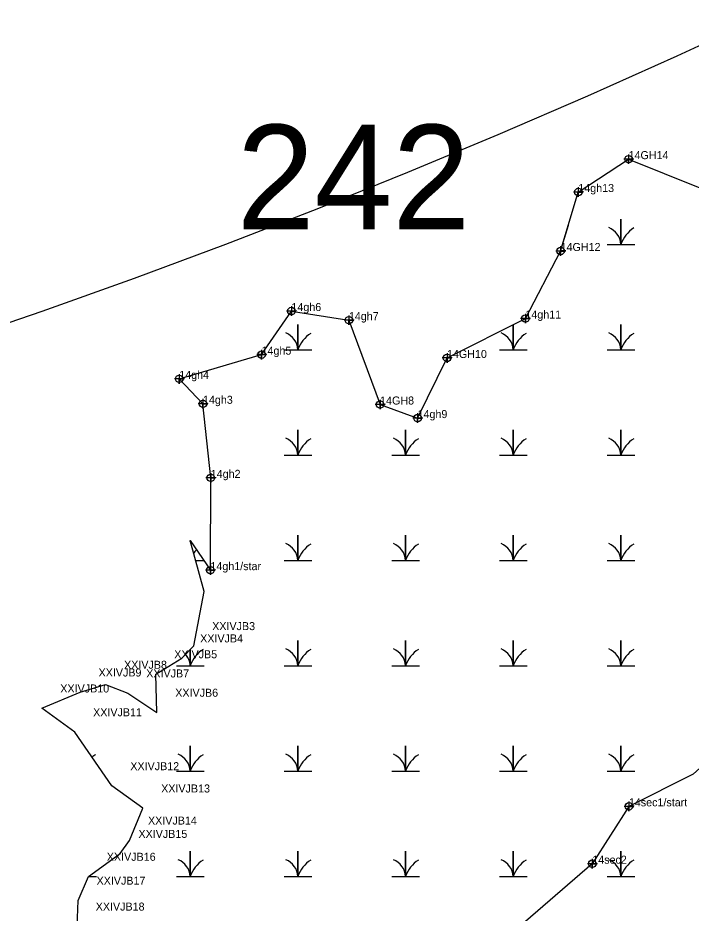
# Model space of a CAD drawing. Extents: x 2071991 to 2268989, y 436479 to 469629.
# Drawn here: x 2263565 to 2263986, y 442642 to 443201 of the extents above; entities that cross this region are included whole.
import ezdxf

# ---------------------------------------------------------------- set-up
doc = ezdxf.new("R2010")
doc.units = 0
for name, color, linetype in [('approx_PSA', 7, 'Continuous'), ('Default', 7, 'Continuous'), ('Exist Environmental Wetland Boundary', 7, 'Continuous'), ('Exist Environmental Wetland Boundary Cogo Comment', 7, 'Continuous'), ('Exist Environmental Wetland Boundary Cogo Point CELL', 7, 'Continuous'), ('Exist Hydro Jurisdictional Stream or Body of Water NEU Mitigable', 7, 'Continuous'), ('Exist Hydro Jurisdictional Stream or Body of Water NEU Mitigable Cogo Comment', 7, 'Continuous'), ('Exist Hydro Jurisdictional Stream or Body of Water NEU Mitigable Cogo Point CELL', 7, 'Continuous'), ('Exist Hydro Swamp or Marsh', 7, 'Continuous')]:
    doc.layers.add(name, color=color, linetype=linetype)

msp = doc.modelspace()

# ---------------------------------------------------------------- linework, layer by layer
at = {"layer": 'approx_PSA'}
for p, q in [((2263976.94, 443176.93), (2264028.06, 443200.63)), ((2263921.24, 443151.98), (2263976.94, 443176.93)), ((2263865.22, 443127.75), (2263921.24, 443151.98)), ((2263808.9, 443104.25), (2263865.22, 443127.75)), ((2263752.27, 443081.48), (2263808.9, 443104.25)), ((2263695.36, 443059.43), (2263752.27, 443081.48)), ((2263638.16, 443038.13), (2263695.36, 443059.43)), ((2263580.7, 443017.56), (2263638.16, 443038.13)), ((2263522.98, 442997.73), (2263580.7, 443017.56))]:
    msp.add_line(p, q, dxfattribs=at)
at = {"layer": 'Exist Environmental Wetland Boundary'}
msp.add_line((2263685.65, 442855.81), (2263685.65, 442855.81), dxfattribs=at)
msp.add_line((2263685.65, 442855.81), (2263685.65, 442855.81), dxfattribs=at)
for points in [[(2263685.65, 442855.81), (2263685.86, 442913.44), (2263681.01, 442959.68), (2263666.2, 442975.24), (2263717.57, 442990.36), (2263736.22, 443017.59), (2263772.08, 443011.89), (2263791.56, 442959.23), (2263814.96, 442950.75), (2263833.34, 442988.29), (2263882.26, 443012.92), (2263904.25, 443055.08), (2263915.31, 443091.9), (2263946.68, 443112.43), (2263991.16, 443094.56), (2264035.37, 443136.43), (2264053.54, 443106.16), (2264094.03, 443128.23), (2264118.46, 443162.37), (2264137.19, 443142.96), (2264168.26, 443124.93), (2264172.08, 443183.66), (2264223.31, 443170.74)], [(2263685.65, 442855.81), (2263685.86, 442913.44), (2263681.01, 442959.68), (2263666.2, 442975.24), (2263717.57, 442990.36), (2263736.22, 443017.59), (2263772.08, 443011.89), (2263791.56, 442959.23), (2263814.96, 442950.75), (2263833.34, 442988.29), (2263882.26, 443012.92), (2263904.25, 443055.08), (2263909.09, 443071.19)], [(2263685.65, 442855.81), (2263685.86, 442913.44), (2263681.01, 442959.68), (2263666.2, 442975.24), (2263717.57, 442990.36), (2263736.22, 443017.59), (2263772.08, 443011.89), (2263791.56, 442959.23), (2263814.96, 442950.75), (2263833.34, 442988.29), (2263882.26, 443012.92), (2263904.25, 443055.08), (2263909.09, 443071.19)], [(2263602.54, 442633.4), (2263603.07, 442649.58), (2263609.46, 442664.49), (2263629.22, 442678.79), (2263635.17, 442687.1), (2263643.39, 442707.13), (2263624.14, 442721.05), (2263600.92, 442754.72), (2263580.43, 442769.57), (2263604.31, 442779.56), (2263620.23, 442784.39), (2263634.07, 442778.97), (2263652.18, 442766.91), (2263651.54, 442790.92), (2263667.74, 442800.84), (2263675.24, 442808.52), (2263681.69, 442842.39), (2263672.9, 442874.42), (2263685.65, 442855.81)]]:
    msp.add_lwpolyline(points, dxfattribs=at)
at = {"layer": 'Exist Environmental Wetland Boundary Cogo Point CELL'}
for points in [[(2263946.68, 443115.43), (2263946.68, 443109.43), (2263946.68, 443112.43), (2263949.68, 443112.43), (2263943.68, 443112.43)], [(2263915.31, 443094.9), (2263915.31, 443088.9), (2263915.31, 443091.9), (2263918.31, 443091.9), (2263912.31, 443091.9)], [(2263904.25, 443058.08), (2263904.25, 443052.08), (2263904.25, 443055.08), (2263907.25, 443055.08), (2263901.25, 443055.08)], [(2263736.22, 443020.59), (2263736.22, 443014.59), (2263736.22, 443017.59), (2263739.22, 443017.59), (2263733.22, 443017.59)], [(2263772.08, 443014.89), (2263772.08, 443008.89), (2263772.08, 443011.89), (2263775.08, 443011.89), (2263769.08, 443011.89)], [(2263882.26, 443015.92), (2263882.26, 443009.92), (2263882.26, 443012.92), (2263885.26, 443012.92), (2263879.26, 443012.92)], [(2263717.57, 442993.36), (2263717.57, 442987.36), (2263717.57, 442990.36), (2263720.57, 442990.36), (2263714.57, 442990.36)], [(2263833.34, 442991.29), (2263833.34, 442985.29), (2263833.34, 442988.29), (2263836.34, 442988.29), (2263830.34, 442988.29)], [(2263666.2, 442978.24), (2263666.2, 442972.24), (2263666.2, 442975.24), (2263669.2, 442975.24), (2263663.2, 442975.24)], [(2263681.01, 442962.68), (2263681.01, 442956.68), (2263681.01, 442959.68), (2263684.01, 442959.68), (2263678.01, 442959.68)], [(2263791.56, 442962.23), (2263791.56, 442956.23), (2263791.56, 442959.23), (2263794.56, 442959.23), (2263788.56, 442959.23)], [(2263814.96, 442953.75), (2263814.96, 442947.75), (2263814.96, 442950.75), (2263817.96, 442950.75), (2263811.96, 442950.75)], [(2263685.86, 442916.44), (2263685.86, 442910.44), (2263685.86, 442913.44), (2263688.86, 442913.44), (2263682.86, 442913.44)], [(2263685.65, 442858.81), (2263685.65, 442852.81), (2263685.65, 442855.81), (2263688.65, 442855.81), (2263682.65, 442855.81)]]:
    msp.add_lwpolyline(points, dxfattribs=at)
for centre in [(2263946.68, 443112.43), (2263915.31, 443091.9), (2263904.25, 443055.08), (2263736.22, 443017.59), (2263772.08, 443011.89), (2263882.26, 443012.92), (2263717.57, 442990.36), (2263833.34, 442988.29), (2263666.2, 442975.24), (2263681.01, 442959.68), (2263791.56, 442959.23), (2263814.96, 442950.75), (2263685.86, 442913.44), (2263685.65, 442855.81)]:
    msp.add_circle(centre, 2.34, dxfattribs=at)
at = {"layer": 'Exist Hydro Jurisdictional Stream or Body of Water NEU Mitigable'}
for points in [[(2264498.91, 443198.38), (2264443.26, 443120.42), (2264356.45, 442986.77), (2264249.6, 442922.17), (2264209.53, 442888.76), (2264158.34, 442862.03), (2264051.49, 442786.29), (2263986.94, 442728.38), (2263946.87, 442708.33)], [(2263946.87, 442708.33), (2263924.02, 442672.5), (2263882.33, 442636.32)]]:
    msp.add_lwpolyline(points, dxfattribs=at)
at = {"layer": 'Exist Hydro Jurisdictional Stream or Body of Water NEU Mitigable Cogo Point CELL'}
for points in [[(2263946.87, 442711.33), (2263946.87, 442705.33), (2263946.87, 442708.33), (2263949.87, 442708.33), (2263943.87, 442708.33)], [(2263924.02, 442675.5), (2263924.02, 442669.5), (2263924.02, 442672.5), (2263927.02, 442672.5), (2263921.02, 442672.5)]]:
    msp.add_lwpolyline(points, dxfattribs=at)
for centre in [(2263946.87, 442708.33), (2263924.02, 442672.5)]:
    msp.add_circle(centre, 2.34, dxfattribs=at)
at = {"layer": 'Exist Hydro Swamp or Marsh'}
for p, q in [((2263673.1, 442873.7), (2263673.1, 442874.13)), ((2263673.1, 442874.13), (2263673.1, 442873.7)), ((2263676.34, 442861.89), (2263681.48, 442861.89)), ((2263609.55, 442664.55), (2263614.5, 442664.55))]:
    msp.add_line(p, q, dxfattribs=at)
for points in [[(2263933.31, 443059.24), (2263941.91, 443059.24), (2263941.91, 443075.02), (2263941.91, 443059.24), (2263950.52, 443059.24)], [(2263731.7, 442993.46), (2263740.3, 442993.46), (2263740.3, 443009.24), (2263740.3, 442993.46), (2263748.91, 442993.46)], [(2263866.11, 442993.46), (2263874.71, 442993.46), (2263874.71, 443009.12)], [(2263874.71, 443009.12), (2263874.71, 442993.46), (2263883.31, 442993.46)], [(2263933.31, 442993.46), (2263941.91, 442993.46), (2263941.91, 443009.24), (2263941.91, 442993.46), (2263950.52, 442993.46)], [(2263731.7, 442927.67), (2263740.3, 442927.67), (2263740.3, 442943.46), (2263740.3, 442927.67), (2263748.91, 442927.67)], [(2263798.91, 442927.67), (2263807.51, 442927.67), (2263807.51, 442943.46), (2263807.51, 442927.67), (2263816.11, 442927.67)], [(2263866.11, 442927.67), (2263874.71, 442927.67), (2263874.71, 442943.46), (2263874.71, 442927.67), (2263883.31, 442927.67)], [(2263933.31, 442927.67), (2263941.91, 442927.67), (2263941.91, 442943.46), (2263941.91, 442927.67), (2263950.52, 442927.67)], [(2263731.7, 442861.89), (2263740.3, 442861.89), (2263740.3, 442877.67), (2263740.3, 442861.89), (2263748.91, 442861.89)], [(2263798.91, 442861.89), (2263807.51, 442861.89), (2263807.51, 442877.67), (2263807.51, 442861.89), (2263816.11, 442861.89)], [(2263866.11, 442861.89), (2263874.71, 442861.89), (2263874.71, 442877.67), (2263874.71, 442861.89), (2263883.31, 442861.89)], [(2263933.31, 442861.89), (2263941.91, 442861.89), (2263941.91, 442877.67), (2263941.91, 442861.89), (2263950.52, 442861.89)], [(2263731.7, 442796.11), (2263740.3, 442796.11), (2263740.3, 442811.89), (2263740.3, 442796.11), (2263748.91, 442796.11)], [(2263798.91, 442796.11), (2263807.51, 442796.11), (2263807.51, 442811.89), (2263807.51, 442796.11), (2263816.11, 442796.11)], [(2263866.11, 442796.11), (2263874.71, 442796.11), (2263874.71, 442811.89), (2263874.71, 442796.11), (2263883.31, 442796.11)], [(2263933.31, 442796.11), (2263941.91, 442796.11), (2263941.91, 442811.89), (2263941.91, 442796.11), (2263950.52, 442796.11)], [(2263664.5, 442796.11), (2263673.1, 442796.11), (2263673.1, 442806.33)], [(2263673.1, 442806.33), (2263673.1, 442796.11), (2263681.7, 442796.11)], [(2263664.5, 442730.33), (2263673.1, 442730.33), (2263673.1, 442746.11), (2263673.1, 442730.33), (2263681.7, 442730.33)], [(2263731.7, 442730.33), (2263740.3, 442730.33), (2263740.3, 442746.11), (2263740.3, 442730.33), (2263748.91, 442730.33)], [(2263798.91, 442730.33), (2263807.51, 442730.33), (2263807.51, 442746.11), (2263807.51, 442730.33), (2263816.11, 442730.33)], [(2263866.11, 442730.33), (2263874.71, 442730.33), (2263874.71, 442746.11), (2263874.71, 442730.33), (2263883.31, 442730.33)], [(2263933.31, 442730.33), (2263941.91, 442730.33), (2263941.91, 442746.11), (2263941.91, 442730.33), (2263950.52, 442730.33)], [(2263664.5, 442664.55), (2263673.1, 442664.55), (2263673.1, 442680.33), (2263673.1, 442664.55), (2263681.7, 442664.55)], [(2263731.7, 442664.55), (2263740.3, 442664.55), (2263740.3, 442680.33), (2263740.3, 442664.55), (2263748.91, 442664.55)], [(2263798.91, 442664.55), (2263807.51, 442664.55), (2263807.51, 442680.33), (2263807.51, 442664.55), (2263816.11, 442664.55)], [(2263866.11, 442664.55), (2263874.71, 442664.55), (2263874.71, 442680.33), (2263874.71, 442664.55), (2263883.31, 442664.55)], [(2263933.31, 442664.55), (2263941.91, 442664.55), (2263941.91, 442680.33), (2263941.91, 442664.55), (2263950.52, 442664.55)]]:
    msp.add_lwpolyline(points, dxfattribs=at)
for centre, radius, start, end in [((2263929.65, 443058.35), 12.3, 4.1403, 67.535), ((2263960.16, 443053.18), 19.22, 122.1274, 161.6222), ((2263728.04, 442992.57), 12.3, 4.1403, 67.535), ((2263758.55, 442987.39), 19.22, 122.1274, 161.6222), ((2263862.44, 442992.57), 12.3, 4.1403, 67.535), ((2263892.95, 442987.39), 19.22, 122.1274, 161.6222), ((2263929.65, 442992.57), 12.3, 4.1403, 67.535), ((2263960.16, 442987.39), 19.22, 122.1274, 161.6222), ((2263728.04, 442926.79), 12.3, 4.1403, 67.535), ((2263758.55, 442921.61), 19.22, 122.1274, 161.6222), ((2263795.24, 442926.79), 12.3, 4.1403, 67.535), ((2263825.75, 442921.61), 19.22, 122.1274, 161.6222), ((2263862.44, 442926.79), 12.3, 4.1403, 67.535), ((2263892.95, 442921.61), 19.22, 122.1274, 161.6222), ((2263929.65, 442926.79), 12.3, 4.1403, 67.535), ((2263960.16, 442921.61), 19.22, 122.1274, 161.6222), ((2263728.04, 442861.01), 12.3, 4.1403, 67.535), ((2263758.55, 442855.83), 19.22, 122.1274, 161.6222), ((2263795.24, 442861.01), 12.3, 4.1403, 67.535), ((2263825.75, 442855.83), 19.22, 122.1274, 161.6222), ((2263862.44, 442861.01), 12.3, 4.1403, 67.535), ((2263892.95, 442855.83), 19.22, 122.1274, 161.6222), ((2263929.65, 442861.01), 12.3, 4.1403, 67.535), ((2263960.16, 442855.83), 19.22, 122.1274, 161.6222), ((2263691.34, 442855.83), 19.22, 138.6021, 147.3614), ((2263691.34, 442790.05), 19.22, 122.1274, 161.6222), ((2263728.04, 442795.23), 12.3, 4.1403, 67.535), ((2263758.55, 442790.05), 19.22, 122.1274, 161.6222), ((2263795.24, 442795.23), 12.3, 4.1403, 67.535), ((2263825.75, 442790.05), 19.22, 122.1274, 161.6222), ((2263862.44, 442795.23), 12.3, 4.1403, 67.535), ((2263892.95, 442790.05), 19.22, 122.1274, 161.6222), ((2263929.65, 442795.23), 12.3, 4.1403, 67.535), ((2263960.16, 442790.05), 19.22, 122.1274, 161.6222), ((2263660.83, 442795.23), 12.3, 4.1403, 40.9312), ((2263624.14, 442724.27), 19.22, 122.1274, 130.0537), ((2263660.83, 442729.45), 12.3, 4.1403, 67.535), ((2263691.34, 442724.27), 19.22, 122.1274, 161.6222), ((2263728.04, 442729.45), 12.3, 4.1403, 67.535), ((2263758.55, 442724.27), 19.22, 122.1274, 161.6222), ((2263795.24, 442729.45), 12.3, 4.1403, 67.535), ((2263825.75, 442724.27), 19.22, 122.1274, 161.6222), ((2263862.44, 442729.45), 12.3, 4.1403, 67.535), ((2263892.95, 442724.27), 19.22, 122.1274, 161.6222), ((2263929.65, 442729.45), 12.3, 4.1403, 67.535), ((2263960.16, 442724.27), 19.22, 122.1274, 161.6222), ((2263660.83, 442663.66), 12.3, 4.1403, 67.535), ((2263691.34, 442658.49), 19.22, 122.1274, 161.6222), ((2263728.04, 442663.66), 12.3, 4.1403, 67.535), ((2263758.55, 442658.49), 19.22, 122.1274, 161.6222), ((2263795.24, 442663.66), 12.3, 4.1403, 67.535), ((2263825.75, 442658.49), 19.22, 122.1274, 161.6222), ((2263862.44, 442663.66), 12.3, 4.1403, 67.535), ((2263892.95, 442658.49), 19.22, 122.1274, 161.6222), ((2263929.65, 442663.66), 12.3, 4.1403, 67.535), ((2263960.16, 442658.49), 19.22, 122.1274, 161.6222)]:
    msp.add_arc(centre, radius, start, end, dxfattribs=at)

# ---------------------------------------------------------------- texts
at = {"layer": 'Default'}
msp.add_text('242', height=65.34, dxfattribs=at).set_placement((2263702.07, 443068.58))
at = {"layer": 'Exist Environmental Wetland Boundary Cogo Comment'}
for s, p in [('14GH14', (2263946.68, 443112.43)), ('14gh13', (2263915.31, 443091.9)), ('14GH12', (2263904.25, 443055.08)), ('14gh6', (2263736.22, 443017.59)), ('14gh7', (2263772.08, 443011.89)), ('14gh11', (2263882.26, 443012.92)), ('14gh5', (2263717.57, 442990.36)), ('14GH10', (2263833.34, 442988.29)), ('14gh4', (2263666.2, 442975.24)), ('14gh3', (2263681.01, 442959.68)), ('14GH8', (2263791.56, 442959.23)), ('14gh9', (2263814.96, 442950.75)), ('14gh2', (2263685.86, 442913.44)), ('14gh1/star', (2263685.65, 442855.81)), ('XXIVJB3 ', (2263686.75, 442818.36)), ('XXIVJB4 ', (2263679.25, 442810.68)), ('XXIVJB5 ', (2263663.06, 442800.77)), ('XXIVJB8 ', (2263631.74, 442794.23)), ('XXIVJB9 ', (2263615.82, 442789.4)), ('XXIVJB7 ', (2263645.58, 442788.81)), ('XXIVJB10 ', (2263591.94, 442779.41)), ('XXIVJB6 ', (2263663.69, 442776.76)), ('XXIVJB11 ', (2263612.43, 442764.56)), ('XXIVJB12 ', (2263635.65, 442730.9)), ('XXIVJB13 ', (2263654.9, 442716.97)), ('XXIVJB14 ', (2263646.68, 442696.95)), ('XXIVJB15 ', (2263640.73, 442688.63)), ('XXIVJB16 ', (2263620.97, 442674.33)), ('XXIVJB17 ', (2263614.58, 442659.42)), ('XXIVJB18 ', (2263614.05, 442643.24))]:
    msp.add_text(s, height=5, dxfattribs=at).set_placement(p)
at = {"layer": 'Exist Hydro Jurisdictional Stream or Body of Water NEU Mitigable Cogo Comment'}
for s, p in [('14sec1/start', (2263946.87, 442708.33)), ('14sec2', (2263924.02, 442672.5))]:
    msp.add_text(s, height=5, dxfattribs=at).set_placement(p)

doc.saveas('drawing.dxf')
